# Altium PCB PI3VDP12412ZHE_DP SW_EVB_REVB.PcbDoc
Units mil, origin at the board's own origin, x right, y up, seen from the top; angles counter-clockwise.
Board outline 3198 x 2598 mil, 4 copper layers (Top Layer, InternalPlane1, InternalPlane2, Bottom Layer); 46 components, 59 nets, 210 pads, 109 vias.
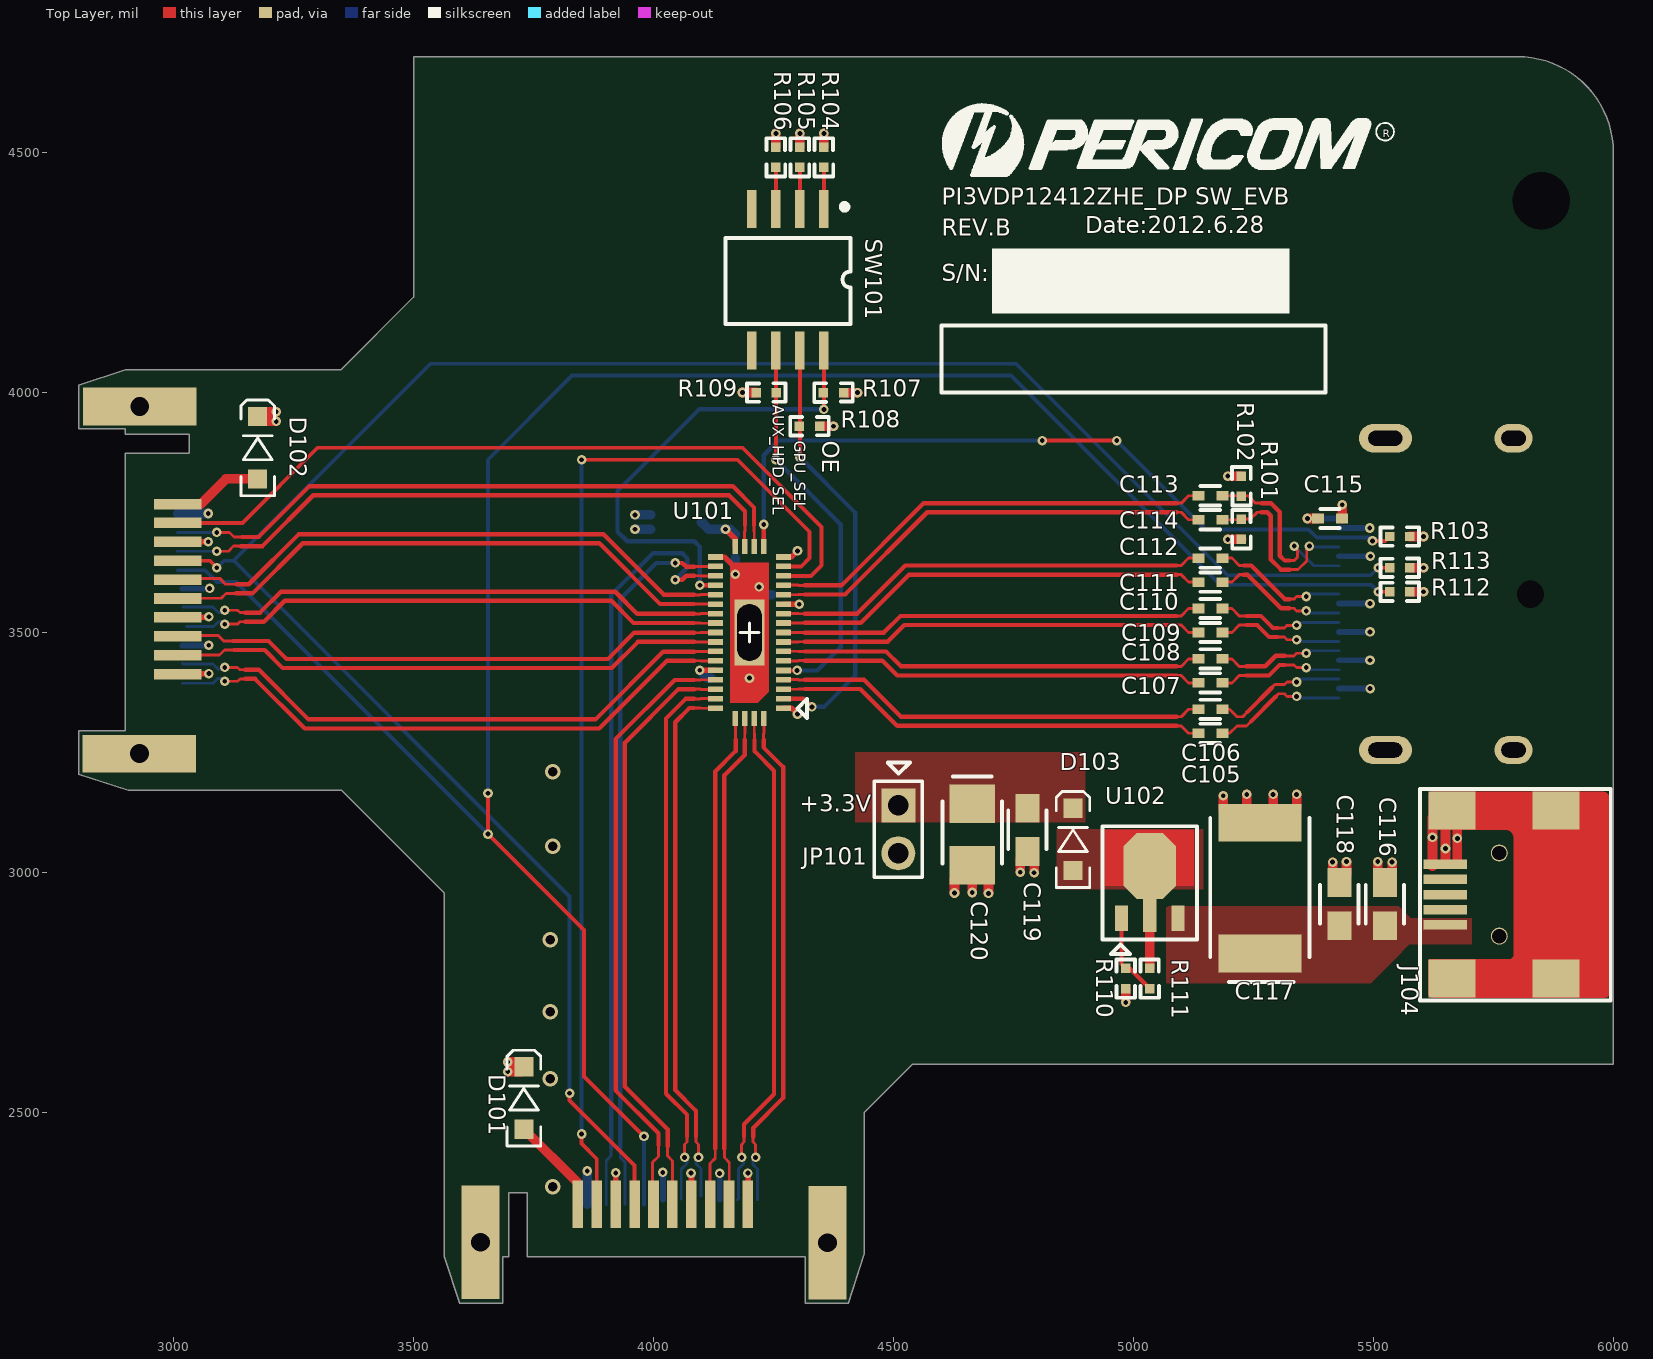
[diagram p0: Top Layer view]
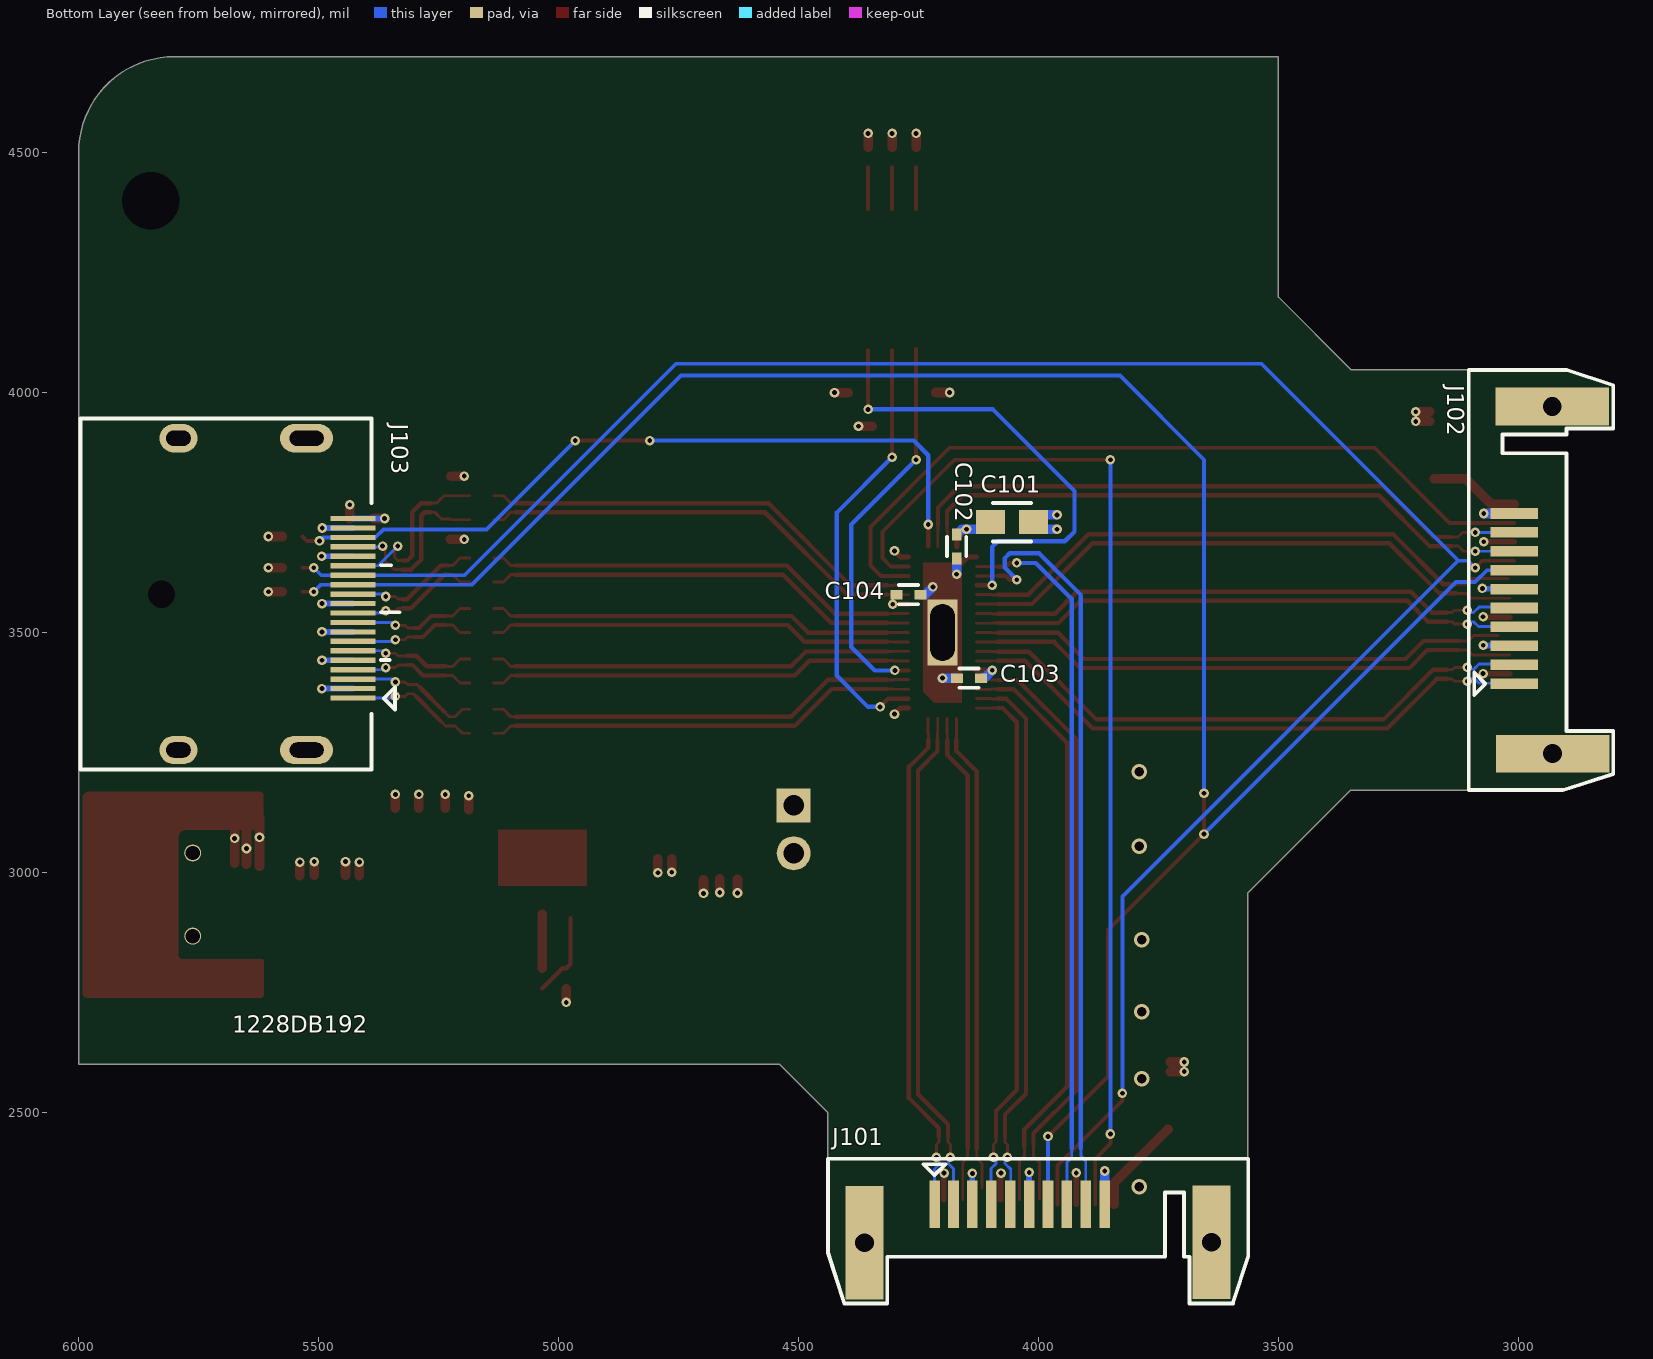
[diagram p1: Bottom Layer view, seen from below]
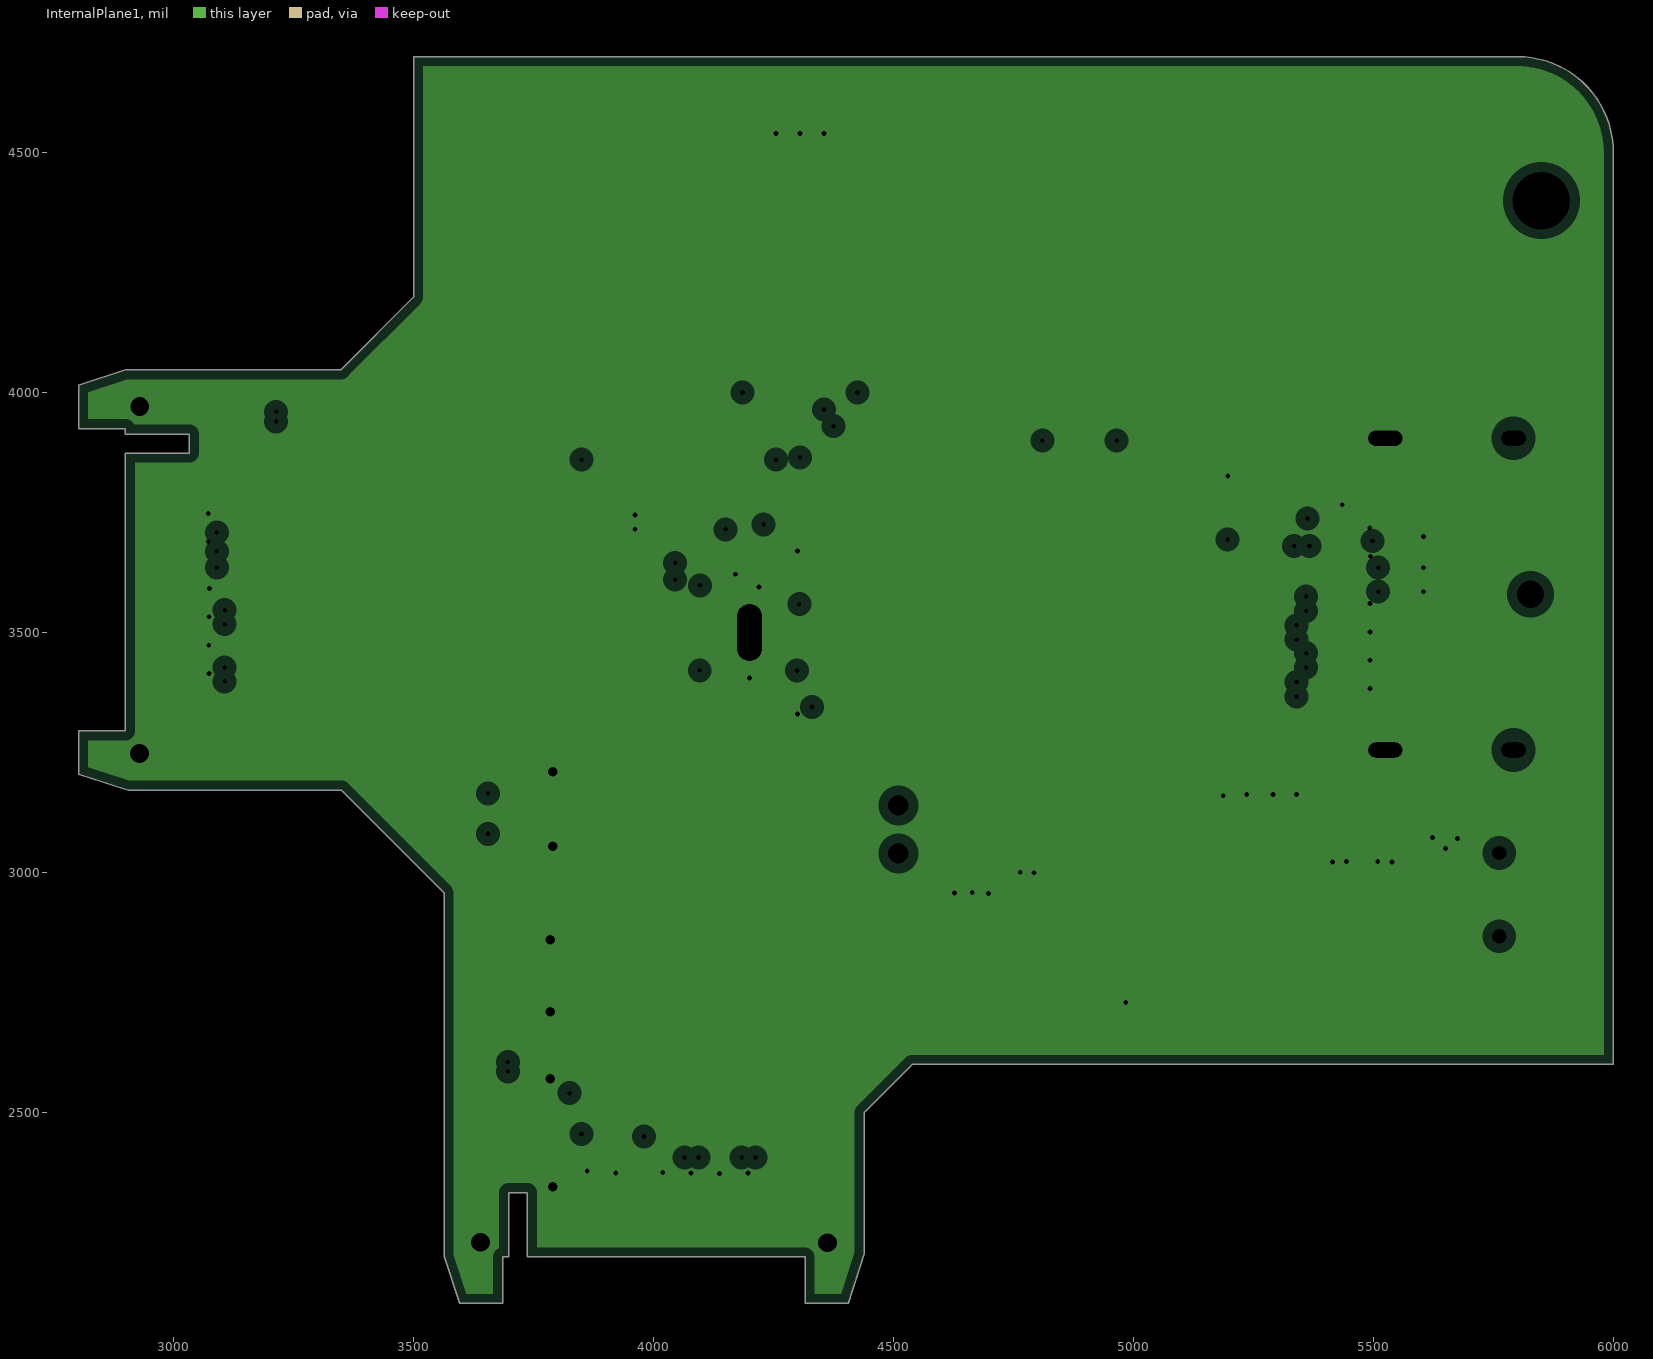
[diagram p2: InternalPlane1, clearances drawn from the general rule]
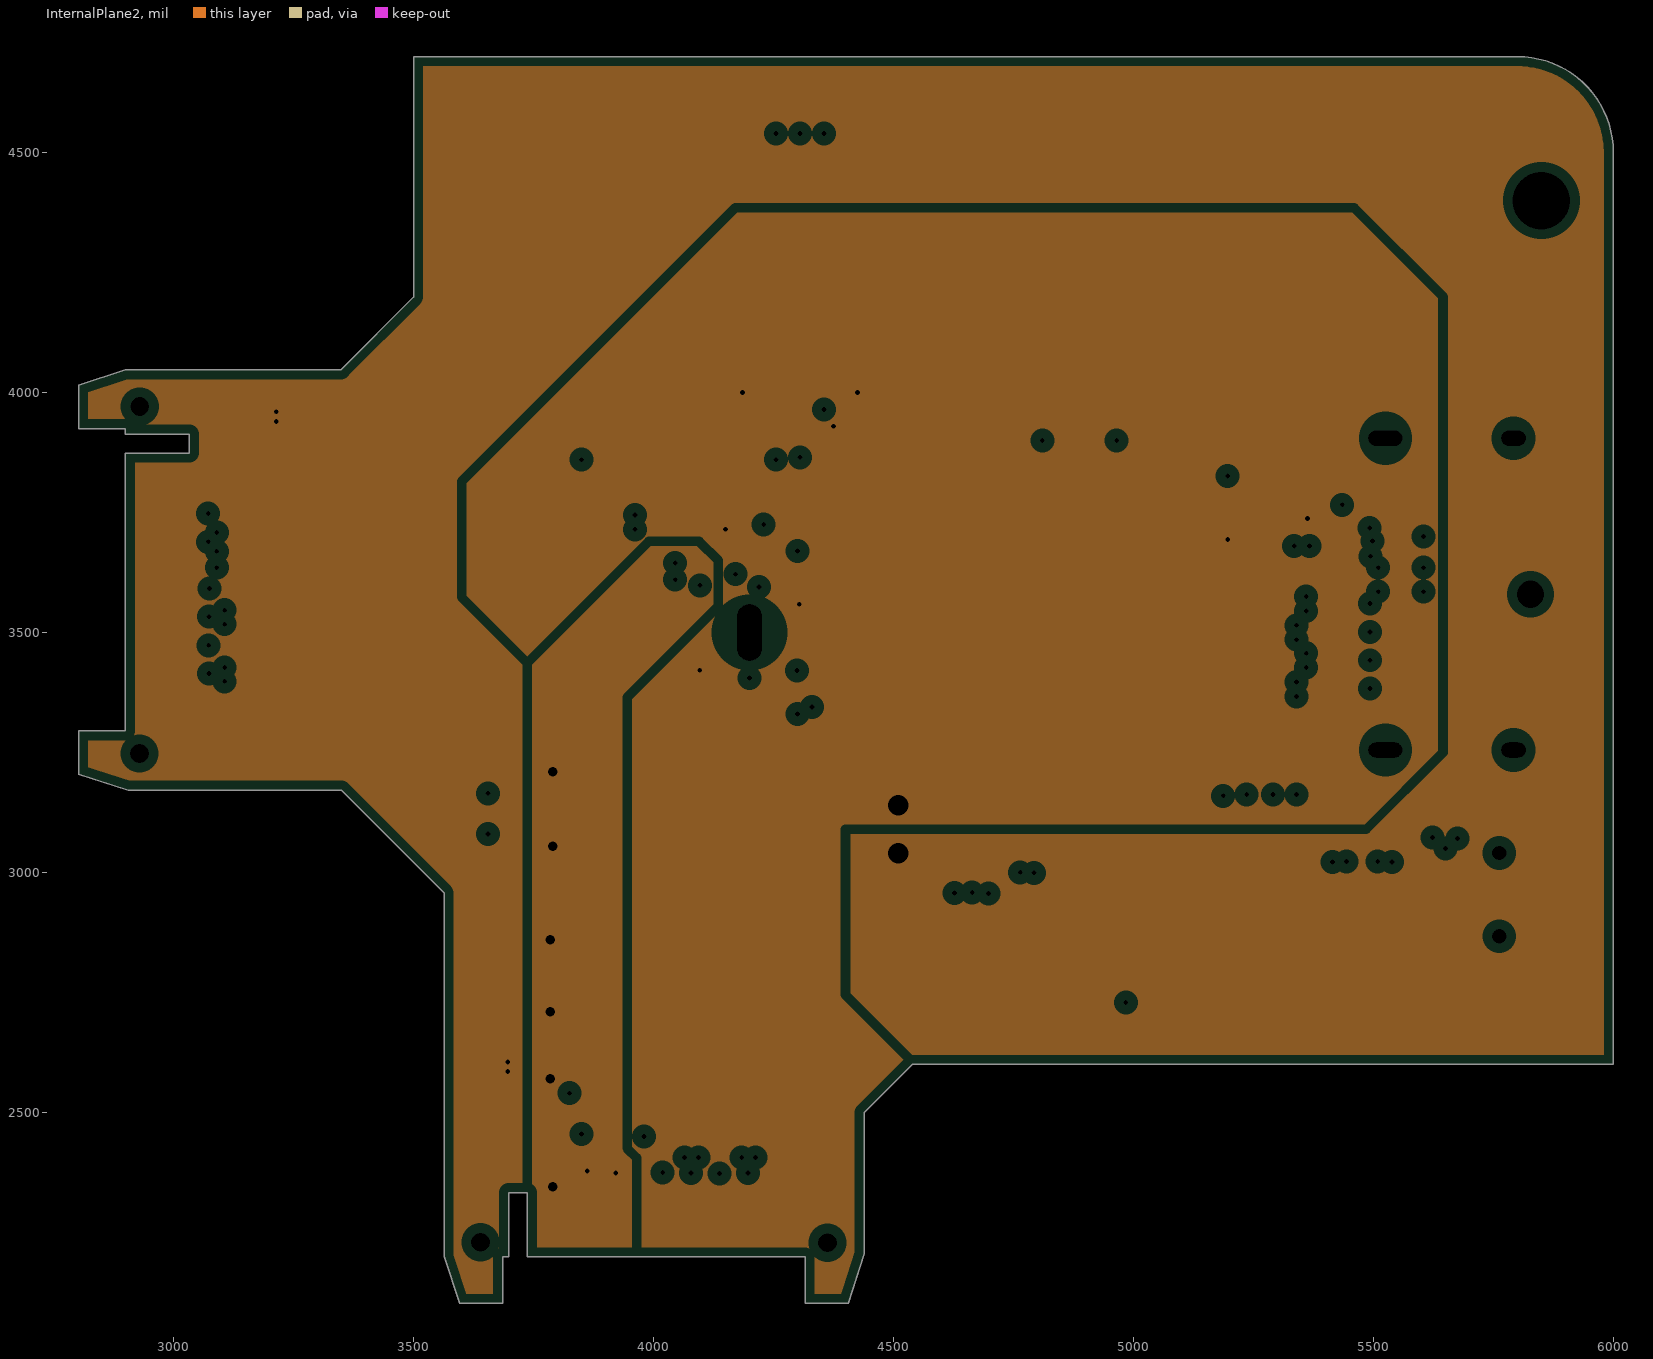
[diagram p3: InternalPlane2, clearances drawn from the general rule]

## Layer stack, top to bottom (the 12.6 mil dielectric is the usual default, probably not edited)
Top Layer: signal copper 1.4
Dielectric: core 12.6, FR-4, Dk 4.8
InternalPlane1: plane copper 1.4, net GND
Dielectric: prepreg 12.6, FR-4, Dk 4.8
InternalPlane2: plane copper 1.4, net +3V3
Dielectric: core 12.6, FR-4, Dk 4.8
Bottom Layer: signal copper 1.4

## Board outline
2802,3205 2802,3295 2899,3295 2899,3874 3033,3874 3033,3913 2899,3913 2899,3925 2802,3925 2802,4015 2899.9,4047.3 3348.3,4047.3 3500,4199 3500,4700 5800,4700 cw(c5800,4500) 6000,4500 6000,2600 4539,2600 4439,2500 4439,2205.6 4405.77,2102 4315.77,2102 4315.77,2199 3736.77,2199 3736.77,2333 3697.77,2333 3697.77,2199 3685.77,2199 3685.77,2102 3595.77,2102 3563.47,2199.9 3563.47,2957.53 3349.23,3171.77 2905.6,3171.77

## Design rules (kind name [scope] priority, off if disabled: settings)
Clearance [All] p1: gap=5
ComponentClearance [All] p1: gap=0 collisioncheckmode=3 verticalgap=0
DiffPairsRouting [All] p1: maxlimit=10 minlimit=10 mostfreqgap=10 maxuncoupledlength=500
PlaneClearance [All] p1: clearance=20
PlaneConnect [All] p1: planeconnectstyle=Direct reliefexpansion=20 reliefentries=4 reliefconductorwidth=10 reliefairgap=10
PolygonConnect [All] p1: connectstyle=Direct reliefconductorwidth=10 reliefentries=4 polygonreliefangle="90 Angle"
RoomDefinition "PI3VDP12412 EVB" [InComponentClass('PI3VDP12412 EVB')] p1: confinementstyle=ConfineIn formatcopy=TRUE lockcomponents=FALSE outline 55,960 20005,960 20005,7005 55,7005
RoutingVias [All] p1: holewidth=28 width=50 viastyle="Through Hole" minholewidth=8 minwidth=10 maxholewidth=28 maxwidth=50
SolderMaskExpansion [All] p1: expansion=4
TestPointUsage [All] p1: valid=0 allowmultiple=FALSE
Testpoint [All] p1: side=15 testpointundercomponent=TRUE minsize=40 maxsize=100 preferedsize=60 minholesize=0 maxholesize=40 preferedholesize=32 testpointgrid=1 style=1023 order=0123456789
Width [All] p1: maxlimit=105 minlimit=5 preferedwidth=10
15 further rules are at their usual default settings.

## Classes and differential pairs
differential pair NewDifferentialPair20: +NetC113_2 -NetC114_2
differential pair NewDifferentialPair19: +NetC111_2 -NetC112_2
differential pair NewDifferentialPair18: +NetC109_2 -NetC110_2
differential pair NewDifferentialPair17: +NetC107_2 -NetC108_2
differential pair NewDifferentialPair16: +NetC105_2 -NetC106_2
differential pair NewDifferentialPair15: +D3+B -D3-B
differential pair NewDifferentialPair14: +D3+A -D3-A
differential pair NewDifferentialPair13: +D3- -D3+
differential pair NewDifferentialPair12: +D2+B -D2-B
differential pair NewDifferentialPair11: +D2+A -D2-A
differential pair NewDifferentialPair10: +D2- -D2+
differential pair NewDifferentialPair9: +D1+B -D1-B
differential pair NewDifferentialPair8: +D1+A -D1-A
differential pair NewDifferentialPair7: +D1- -D1+
differential pair NewDifferentialPair6: +D0-B -D0+B
differential pair NewDifferentialPair5: +D0+A -D0-A
differential pair NewDifferentialPair4: +D0+ -D0-
differential pair NewDifferentialPair3: +AUX+B -AUX-B
differential pair NewDifferentialPair2: +AUX+A -AUX-A
differential pair NewDifferentialPair1: +AUX+ -AUX-

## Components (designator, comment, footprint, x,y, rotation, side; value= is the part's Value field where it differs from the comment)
C101 "4.7u" CC_0805 4055,3730 r0 bottom
C102 "1u" CC_0402 4170.47,3679.13 r90 bottom
C103 "0.1u" CC_0402 4145,3405 r180 bottom
C104 "0.1u" CC_0402 4270.87,3578.74 r0 bottom
C105 "0.1u" CC_0402 5160,3290 r0 top
C106 "0.1u" CC_0402 5160,3340 r0 top
C107 "0.1u" CC_0402 5160,3395 r0 top
C108 "0.1u" CC_0402 5160,3445 r0 top
C109 "0.1u" CC_0402 5160,3500 r0 top
C110 "0.1u" CC_0402 5160,3550 r0 top
C111 "0.1u" CC_0402 5160,3605 r0 top
C112 "0.1u" CC_0402 5160,3655 r0 top
C113 "0.1u" CC_0402 5160,3785 r0 top
C114 "0.1u" CC_0402 5160,3735 r0 top
C115 "0.1u" CC_0402 5410,3737.48 r180 top
C116 "4.7u" CC_0805 5524,2934 r90 top
C117 "100u" CAP@CT_7343 5264,2949 r270 top
C118 "1u" CAP@CC_0805 5429,2934 r90 top
C119 "1u" CAP@CC_0805 4779,3089 r270 top
C120 "22u" CAP@CT_3528 4664,3079 r270 top
D101 "B0520LW" D@SOD-123 3730,2530 r90 top
D102 "B0520LW" D@SOD-123 3175,3885 r90 top
D103 "B0520LW" D@SOD-123 4874,3069 r90 top
J101 "DP PLUG" CON_DP_PLUG 4000,2210 r0 bottom
J102 "DP PLUG" CON_DP_PLUG 2910,3610 r270 bottom
J103 "CON_DP_Source_Recept" CON_DP_Recept 5625,3580 r270 bottom
J104 "CON_USB2.0_MiniB_SMT" CON_USB2.0_MiniB_SMT 5969,2954 r180 top
JP101 "2x1 Pin Header" "2x1 Pin Header" 4510,3140 r270 top
R101 "100K" R_0402 5225,3805 r270 top
R102 "100K" R_0402 5225,3715 r90 top
R103 "100K" R_0402 5555,3700 r180 top
R104 "4K7" R_0402 4355,4490 r90 top
R105 "4K7" R_0402 4305,4490 r90 top
R106 "4K7" R_0402 4255,4490 r90 top
R107 "4K7" RES@R_0402 4375,4000 r0 top
R108 "4K7" RES@R_0402 4325,3930 r0 top
R109 "4K7" RES@R_0402 4235,4000 r180 top
R110 "0" RES@R_0402 4984,2779 r90 top
R111 "NP" RES@R_0402 5034,2779 r90 top
R112 "1M" RES@R_0402 5555,3585 r180 top
R113 "1M" RES@R_0402 5555,3635 r180 top
SW101 "SW_X4_Half_Pitch" SW_X4_Half_Pitch 4280,4235 r180 top
U101 "PI3VDP12412" TQFN42 4200,3500 r90 top locked
U102 "REG1117-3.3V" Pow_SOT_89 5034,2959 r0 top
? "Comment" PSC_LOG 4710,4555 r0 top
? "" "Lable Hole" 5850,4400 r0 top

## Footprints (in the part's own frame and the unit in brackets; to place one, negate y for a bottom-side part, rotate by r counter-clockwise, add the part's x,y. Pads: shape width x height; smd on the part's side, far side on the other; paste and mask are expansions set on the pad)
"2x1 Pin Header" [mm] "Pin Header 2x1 Pitch 2.54mm"
  rect 1.8x1.8 hole 1.1: 1(0,0)
  round 1.8 hole 1.1: 2(2.54,0)
  silkscreen extent -2.27,-1.27 3.81,1.27
CAP@CC_0805 [mil]
  rect 60x50 smd: 1(-45,0) 2(45,0)
  silkscreen extent -40,-40 40,40
CAP@CT_3528 [mil]
  rect 80x95 smd: 1(-64,0) 2(64,0)
  silkscreen extent -121,-62 60,62
CAP@CT_7343 [mm]
  rect 2x4.4 smd: 1(3,0) 2(-3.926,-0.011)
  silkscreen extent -4.19,-2.64 4.5,2.62
CC_0402 [mil]
  rect 25x20 smd: 1(-25,0) 2(25,0)
  silkscreen extent -20,-20 20,20
CC_0805 [mil]
  rect 60x50 smd: 1(-45,0) 2(45,0)
  silkscreen extent -40,-40 40,40
CON_DP_PLUG [mm]
  rect 0.56x2.5 smd: 1(5.495,-2.5) 3(4.495,-2.5) 5(3.495,-2.5) 7(2.495,-2.5) 9(1.495,-2.5) 11(0.495,-2.5) 13(-0.505,-2.5) 15(-1.505,-2.5) 17(-2.505,-2.5) 19(-3.505,-2.5)
  rect 0.56x2.5 smd far side: 2(4.995,-2.5) 4(3.995,-2.5) 6(2.995,-2.5) 8(1.995,-2.5) 10(0.995,-2.5) 12(-0.005,-2.5) 14(-1.005,-2.5) 16(-2.005,-2.5) 18(-3.005,-2.5) 20(-4.005,-2.5)
  rect 2x6 hole 1: 21(-9.166,-0.493) 21(9.206,-0.469)
  silkscreen extent -11.11,-4.92 11.14,2.74
CON_DP_Recept [mm]
  rect 0.28x2.4 smd: 1(5.5,5) 2(5,5) 3(4.5,5) 4(4,5) 5(3.5,5) 6(3,5) 7(2.5,5) 8(2,5) 9(1.5,5) 10(1,5) 11(0.5,5) 12(0,5) 13(-0.5,5) 14(-1,5) 15(-1.5,5) 16(-2,5) 17(-2.5,5) 18(-3,5) 19(-3.5,5) 20(-4,5)
  oval 1.5x2.8 hole 0.8 slot 1.8 at 90 deg: 21(-8.25,2.54) 22(8.25,2.54)
  oval 1.5x2 hole 0.8 slot 1.3 at 90 deg: 23(-8.25,-4.24) 24(8.25,-4.24)
  round 0 hole 1.45 unplated: 25(0,-5.14)
  silkscreen extent -9.29,-9.42 9.28,7.47
CON_USB2.0_MiniB_SMT [mm]
  rect 2.3x0.5 smd: 1(8.1,1.6) 2(8.1,0.8) 3(8.1,0) 4(8.1,-0.8) 5(8.1,-1.6)
  rect 2.5x2 smd: 5(2.25,4.45) 5(2.25,-4.45) 5(7.75,-4.45) 5(7.75,4.45)
  round 0.9 hole 0.762 unplated: 10(5.25,-2.2) 11(5.25,2.2)
  Top Layer region: 1.58,5.45 -0.35,5.45 -0.438,5.432 -0.513,5.383 -0.562,5.308 -0.58,5.22 -0.58,5.22 -0.58,-5.09 -0.553,-5.224 -0.477,-5.337 -0.364,-5.413 -0.23,-5.44 -0.23,-5.44 8.81,-5.44 8.875,-5.427 8.93,-5.39 8.967,-5.335 8.98,-5.27 8.98,-5.27 8.98,-3.59 8.968,-3.529 8.933,-3.477 8.881,-3.442 8.82,-3.43 8.82,-3.43 4.93,-3.43 4.758,-3.396 4.612,-3.298 4.514,-3.152 4.48,-2.98 4.48,-2.98 4.48,3.17 4.5,3.269 4.556,3.354 4.641,3.41 4.74,3.43 4.74,3.43 8.93,3.43 8.964,3.437 8.994,3.456 9.013,3.486 9.02,3.52 9.02,3.52 9.02,5.26 9.004,5.34 8.958,5.408 8.89,5.454 8.81,5.47 8.81,5.47 1.6,5.47 1.592,5.468 1.586,5.464 1.582,5.458 1.58,5.45
  silkscreen extent -0.65,-5.59 9.45,5.6
D@SOD-123 [mil]
  rect 40x40 smd: 1(-65,0) 2(65,0)
  silkscreen extent -100,-35 100,35
"Lable Hole" [mil]
  round 0 hole 120 unplated: ""(0,0)
Pow_SOT_89 [mm] "SOT-89; Body 4.6 x 4.25 mm, inc. leads (LxW max)"
  rect 0.7x1.35 smd: 1(-1.5,-1.388) 3(1.5,-1.388)
  rect 0.7x1.9 smd: 2(0,-1.163)
  oct 2.8x3.5 smd: 2(0,1.388)
  Top Layer region: -2.346,0.336 -2.346,3.302 2.322,3.302 2.323,3.303 2.323,0.338 2.325,0.336
  silkscreen extent -2.5,-3.28 2.5,3.49
PSC_LOG [mil]
  silkscreen extent -107,-103 833,45
R_0402 [mm]
  rect 0.5x0.5 smd: 1(-0.532,-0.001) 2(0.54,-0.001)
  silkscreen extent -1.02,-0.49 1.02,0.49
RES@R_0402 [mm]
  rect 0.5x0.5 smd: 1(-0.532,-0.001) 2(0.54,-0.001)
  silkscreen extent -1.02,-0.49 1.02,0.49
SW_X4_Half_Pitch [mm]
  rect 0.5x2 smd: 1(-1.905,-3.75) 2(-0.635,-3.75) 3(0.635,-3.75) 4(1.905,-3.75) 5(1.905,3.75) 6(0.635,3.75) 7(-0.635,3.75) 8(-1.905,3.75)
  silkscreen extent -3.31,-4.01 3.31,2.34
TQFN42 [mm]
  rect 0.3x0.8 smd: 1(-4,-1.8) 2(-3.5,-1.8) 3(-3,-1.8) 4(-2.5,-1.8) 5(-2.007,-1.8) 6(-1.5,-1.8) 7(-1,-1.8) 8(-0.5,-1.8) 9(0,-1.8) 10(0.5,-1.8) 11(1,-1.8) 12(1.5,-1.8) 13(2,-1.8) 14(2.5,-1.8) 15(3,-1.8) 16(3.5,-1.8) 17(4,-1.8) 22(4,1.8) 23(3.5,1.8) 24(3,1.8) 25(2.5,1.8) 26(2.007,1.8) 27(1.5,1.8) 28(1,1.8) 29(0.5,1.8) 30(0,1.8) 31(-0.5,1.8) 32(-1,1.8) 33(-1.5,1.8) 34(-2,1.8) 35(-2.5,1.8) 36(-3,1.8) 37(-3.5,1.8) 38(-4,1.8)
  rect 0.8x0.3 smd: 18(4.55,-0.75) 19(4.55,-0.25) 20(4.55,0.25) 21(4.55,0.75) 39(-4.55,0.75) 40(-4.55,0.25) 41(-4.55,-0.25) 42(-4.55,-0.75)
  rect 3.5x1.6 hole 1.3 slot 3 at 0 deg: 43(0,0)
  Top Layer region: -3.72,1.01 3.7,1.01 3.7,-1.01 -3.14,-1.01 -3.72,-0.43
  silkscreen extent -4.52,-3.05 0.5,0.5

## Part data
C101 C102 C103 C104 C105 C106 C107 C108 C109 C110 C111 C112 C113 C114 C115: library part C_0.1u_0402
C116 C118 C119: library part "CHIP CAP0805"
C117: library part "100UF 7343_1"
C120: library part "22UF 3528"
D101 D102 D103: library part SchottkyDiode@SOD-123_1
J101: library part CONN_DP_1
J102: library part CONN_DP_0
J103: library part CON_DP_Source_Recept_1
R101 R102 R103 R104 R105 R106: library part R_0402
R107 R108 R109 R110 R111 R112 R113: library part "CHIP RES0402_1"
U101: library part PI3PCIE3412ZHE@TQFN42_1
U102: library part REG1117ADJ@SOT89

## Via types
v1: diameter 20, hole 10, Top Layer to Bottom Layer, tented both sides, 103 vias
v2: diameter 32, hole 20, Top Layer to Bottom Layer, tented both sides, 6 vias

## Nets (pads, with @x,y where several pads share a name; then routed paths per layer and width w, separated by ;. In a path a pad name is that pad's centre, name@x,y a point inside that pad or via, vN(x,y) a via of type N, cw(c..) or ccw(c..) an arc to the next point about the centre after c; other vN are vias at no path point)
+3V3: C101.2 C102.2 C103.2 C104.2 C115.2 C119.1 C120.1 D103.2 J103.20 JP101.1 R102.1 R107.2 R108.2 R109.2 U101.12 U101.21 U101.34 | length 424.7
  Top Layer w12: v1(4096.26,3421.26) U101.34 ; v1(4150,3715) 4170.47,3694.53 U101.21 ; U101.12 v1(4303.74,3559.05)
  Top Layer w20: v1(4185.03,4000.03) R109.2 ; R108.2 v1(4374.97,3929.97) ; R107.2 v1(4424.97,3999.97) ; v1(5196.33,3694.05) R102.1 ; v1(5362.48,3737.48) C115.2
  Bottom Layer w12: v1(5362.48,3737.48) J103.20
  Bottom Layer w20: v1(4096.26,3421.26) 4112.52,3405 C103.2 ; C101.2 4115,3715 4159.61,3715 C102.2
+3V3_A: D101.1 J101.20 | length 203.1
  Top Layer w20: D101.1 3842.32,2352.68 J101.20
+3V3_B: D102.1 J102.20 | length 188.2
  Top Layer w20: J102.20 3056.6,3767.68 3108.92,3820 D102.1
+3V3_USB: D103.1 R111.2 U102.2 | length 112.9
  Top Layer w20: R111.2 U102.2@5034.03,2913.18
+5V: C116.1 C117.1 C118.1 J104.1 U102.3
AUX+: C113.1 U101.14 | length 941.7
  Top Layer w6: U101.14@4270.87,3598.7 4301.61,3598.7 4302.09,3598.22 4314.94,3598.22 ; 5089.93,3769.5 5099.5,3769.5 5115,3785 C113.1
  Top Layer w9: 4314.94,3598.22 4391.35,3598.22 4562.63,3769.5 5089.93,3769.5
AUX+A: J101.15 U101.23 | length 1498.8
  Top Layer w6: 4085.06,3637.32 4097.91,3637.32 4098.39,3637.8 U101.23
  Top Layer w9: v1(4045,3645) 4060,3645 4065,3640 4067.68,3637.32 4085.06,3637.32
  Bottom Layer w6: 3930.56,2425.2 3930.56,2406.49 3940.75,2396.3 J101.15
  Bottom Layer w9: 3930.56,2425.2 3930.56,3535.56 3930.56,3570.06 4005.5,3645 v1(4045,3645)
AUX+B: J102.15 U101.20 | length 1317.9
  Top Layer w6: v1(3090,3669.25) 3114.25,3669.25 3125,3680 3140.03,3680 ; U101.20@4189.88,3679.13 4189.88,3709.88 4190.36,3710.36 4190.36,3723.21
  Top Layer w9: 3140.03,3680 3185,3680 3291.01,3786 4157.13,3786 4190.36,3752.77 4190.36,3723.21
  Bottom Layer w6: J102.15 v1(3090,3669.25)
AUX-: C114.1 U101.13 | length 941.7
  Top Layer w6: U101.13 4301.61,3578.74 4302.09,3579.22 4314.94,3579.22 ; 5090.06,3750.5 5099.5,3750.5 5115,3735 C114.1
  Top Layer w9: 4314.94,3579.22 4399.22,3579.22 4570.5,3750.5 5090.06,3750.5
AUX-A: J101.17 U101.24 | length 1615.8
  Top Layer w6: 4085.06,3618.32 4097.91,3618.32 4098.39,3617.83 U101.24@4129.13,3617.83
  Top Layer w9: v1(4045,3610) 4060,3610 4068.31,3618.31 4085.06,3618.32
  Bottom Layer w6: J101.17 3901.38,2399.46 3911.56,2409.65 3911.56,2425.47
  Bottom Layer w9: 3911.56,2425.2 3911.56,3543.43 3911.56,3577.93 3998.63,3665 4060,3665 4070,3655 4070,3635 v1(4045,3610)
AUX-B: J102.17 U101.19 | length 1348.9
  Top Layer w6: v1(3090,3708.62) 3116.38,3708.62 3126,3699 3141.99,3699 ; 4209.36,3723.21 4209.36,3710.36 4209.84,3709.88 U101.19
  Top Layer w9: 3141.99,3699 3177.13,3699 3283.14,3805 4165,3805 4209.36,3760.64 4209.36,3723.21
  Bottom Layer w6: J102.17 v1(3090,3708.62)
AUX_HPD_SEL: R109.1 SW101.6 U101.5 | length 815.4
  Top Layer w9: v1(4255,3860) SW101.6@4255,4090 ; U101.5 v1(4299.02,3420.98)
  Bottom Layer w9: v1(4255,3860) 4390,3725 4390,3470 4340.98,3420.98 v1(4299.02,3420.98)
CAB_DET: J101.13 J102.13 J103.13 R112.2 | length 4698.4
  Top Layer w8: v1(3655,3165) v1(3655,3080) 3855,2880 3855,2575.12 v1(3980.12,2450) ; v1(5510,3585) R112.2
  Bottom Layer w8: J102.13 3065.12,3629.88 3090,3605 3130,3605 v1(3655,3080) ; v1(3655,3165) 3655,3860 3830.25,4035.25 4744.75,4035.25 5180.31,3599.68 5495.31,3599.68 v1(5510,3585) ; J101.13 v1(3980.12,2450)
CEC: J101.14 J102.14 J103.14 R113.2 | length 4583.3
  Top Layer w8: J102.14 3075.43,3649.57 v1(3090,3635) ; v1(3825,2540) 3825,2525 3960.43,2389.57 J101.14 ; v1(5510,3635) R113.2
  Bottom Layer w8: v1(3090,3635) 3104.57,3649.57 3124.57,3649.57 3535,4060 4755,4060 5195.63,3619.37 J103.14 5494.37,3619.37 v1(5510,3635) ; 3125.43,3649.57 3825,2950 v1(3825,2540)
D0+: C105.1 U101.3 | length 902.5
  Top Layer w6: U101.3 4301.61,3381.89 4302.09,3382.37 4314.94,3382.37 ; 5090.06,3305.5 5099.5,3305.5 5115,3290 C105.1
  Top Layer w9: 4314.94,3382.37 4430.76,3382.37 4507.63,3305.5 5089.93,3305.5
D0+A: J101.1 U101.42 | length 1054.5
  Top Layer w6: 4207.6,2449.39 4207.6,2438.39 4212.6,2433.39 v1(4212.6,2406.39) ; 4229.32,3276.79 4229.32,3289.64 4229.8,3290.12 U101.42@4229.8,3320.87
  Top Layer w9: 4207.6,2449.39 4207.6,2467.6 4270,2530 4270,3220 4229.32,3260.68 4229.32,3276.79
  Bottom Layer w6: v1(4212.6,2406.39) 4206.61,2400.4 4206.61,2392 4216.8,2381.82 J101.1@4216.8,2318
D0+B: J102.1 U101.33 | length 1221.4
  Top Layer w6: v1(3106.39,3398.4) 3133.39,3398.4 3138.39,3403.4 3149.39,3403.4 ; 4085.06,3441.15 4097.91,3441.15 4098.39,3440.67 U101.33@4129.13,3440.67
  Top Layer w9: 3149.39,3403.4 3169.73,3403.4 3273.13,3300 3886.87,3300 4028.02,3441.15 4085.06,3441.15
  Bottom Layer w6: J102.1@3018,3394.2 3081.82,3394.2 3092,3404.39 3100.4,3404.39 v1(3106.39,3398.4)
D0-: C106.1 U101.4 | length 902.6
  Top Layer w6: U101.4@4270.87,3401.85 4301.61,3401.85 4302.09,3401.37 4314.94,3401.37 ; 5089.93,3324.5 5099.5,3324.5 5115,3340 C106.1
  Top Layer w9: 4314.94,3401.37 4438.63,3401.37 4515.5,3324.5 5089.93,3324.5
D0-A: J101.3 U101.41 | length 1054.7
  Top Layer w6: v1(4183.6,2406.39) 4183.6,2433.39 4188.6,2438.39 4188.6,2449.39 ; U101.41 4209.84,3290.12 4210.32,3289.64 4210.32,3276.79
  Top Layer w9: 4188.6,2449.39 4188.6,2475.47 4251,2537.87 4251,3212.13 4210.32,3252.81 4210.32,3276.79
  Bottom Layer w6: J101.3@4175.11,2318 4176.61,2319.5 4176.61,2382 4187.61,2393 4187.61,2402.37 v1(4183.6,2406.39)
D0-B: J102.3 U101.32 | length 1221.5
  Top Layer w6: v1(3106.39,3427.4) 3133.39,3427.4 3138.39,3422.4 3149.39,3422.4 ; 4085,3460.15 4097.91,3460.15 4098.39,3460.63 U101.32
  Top Layer w9: 3149.39,3422.4 3177.6,3422.4 3281,3319 3879,3319 4020.15,3460.15 4085,3460.15
  Bottom Layer w6: J102.3@3018,3435.89 3019.5,3434.39 3082,3434.39 3093,3423.39 3102.37,3423.39 v1(3106.39,3427.4)
D1+: C107.1 U101.6 | length 883.4
  Top Layer w6: U101.6 4301.61,3440.94 4302.09,3441.43 4314.94,3441.43 ; 5090.06,3410.5 5099.5,3410.5 5115,3395 C107.1
  Top Layer w9: 4314.94,3441.43 4476.7,3441.43 4507.63,3410.5 5089.93,3410.5
D1+A: J101.4 U101.40 | length 1024.8
  Top Layer w6: 4147.56,2425 4147.56,2406 4157.74,2395.82 J101.4@4157.74,2318 ; 4189.95,3276.79 4189.95,3289.64 4190.43,3290.12 U101.40@4190.43,3320.87
  Top Layer w9: 4147.55,2425 4147.56,3202.56 4189.95,3244.95 4189.95,3276.79
D1+B: J102.4 U101.31 | length 1153.6
  Top Layer w6: J102.4@3018,3453.26 3095.82,3453.26 3106,3463.44 3125,3463.44 ; 4085.06,3480.52 4097.91,3480.52 4098.39,3480.04 U101.31@4129.13,3480.04
  Top Layer w9: 3125,3463.44 3156.47,3463.44 3189.69,3463.44 3227.13,3426 3912.87,3426 3967.39,3480.52 4085.06,3480.52
D1-: C108.1 U101.7 | length 883.6
  Top Layer w6: U101.7@4270.87,3460.91 4301.61,3460.91 4302.09,3460.43 4315,3460.43 ; 5089.93,3429.5 5099.5,3429.5 5115,3445 C108.1
  Top Layer w9: 4315,3460.43 4484.57,3460.43 4515.5,3429.5 5089.93,3429.5
D1-A: J101.6 U101.39 | length 999.3
  Top Layer w6: J101.6@4117.61,2342.5 4117.61,2393.57 4128.56,2404.51 4128.56,2423.68 ; U101.39 4170.47,3290.12 4170.95,3289.64 4170.95,3276.79
  Top Layer w9: 4128.55,2425 4128.56,3210.43 4170.95,3252.82 4170.95,3276.79
D1-B: J102.6 U101.30 | length 1129.5
  Top Layer w6: J102.6@3042.5,3493.39 3093.57,3493.39 3104.51,3482.44 3123.68,3482.44 ; 4085.06,3499.52 4097.91,3499.52 4098.39,3500 U101.30
  Top Layer w9: 3123.68,3482.44 3197.56,3482.45 3235,3445 3905,3445 3959.52,3499.52 4085.06,3499.52
D2+: C109.1 U101.8 | length 885
  Top Layer w6: U101.8 4301.61,3480.32 4302.09,3480.8 4314.94,3480.8 ; 5090.06,3515.5 5099.5,3515.5 5115,3500 C109.1
  Top Layer w9: 4314.94,3480.8 4487.67,3480.8 4522.37,3515.5 5089.93,3515.5
D2+A: J101.7 U101.38 | length 1109.7
  Top Layer w6: 4085.06,3342.72 4097.91,3342.72 4098.39,3342.24 U101.38@4129.13,3342.24 ; 4088.6,2449.39 4088.6,2438.39 4093.6,2433.39 v1(4093.6,2406.39)
  Top Layer w9: 4085.06,3342.72 4074.59,3342.72 4045,3313.13 4045,2546.87 4088.6,2503.27 4088.6,2480.15 4088.6,2449.39
  Bottom Layer w6: v1(4093.6,2406.39) 4088.5,2401.29 4088.5,2393.18 4098.69,2383 J101.7@4098.69,2326.5
D2+B: J102.7 U101.29 | length 1148.4
  Top Layer w6: v1(3106.39,3517.4) 3133.39,3517.4 3138.39,3522.4 3149.39,3522.4 ; 4085.06,3519.89 4097.91,3519.89 4098.39,3519.41 U101.29@4129.13,3519.41
  Top Layer w9: 3149.39,3522.4 3188.02,3522.4 3231.62,3566 3912.13,3566 3958.24,3519.89 4085.06,3519.89
  Bottom Layer w6: J102.7@3026.5,3512.31 3083,3512.31 3093.18,3522.5 3101.29,3522.5 v1(3106.39,3517.4)
D2-: C110.1 U101.9 | length 885.1
  Top Layer w6: U101.9@4270.87,3500.28 4301.61,3500.28 4302.09,3499.8 4314.94,3499.8 ; 5089.93,3534.5 5099.5,3534.5 5115,3550 C110.1
  Top Layer w9: 4314.94,3499.8 4479.8,3499.8 4514.5,3534.5 5089.93,3534.5
D2-A: J101.9 U101.37 | length 1148.6
  Top Layer w6: v1(4064.6,2406.39) 4064.6,2433.39 4069.6,2438.39 4069.6,2449.39 ; 4085.06,3361.72 4097.91,3361.72 4098.39,3362.2 U101.37
  Top Layer w9: 4069.6,2449.39 4069.6,2495.4 4026,2539 4026,3321 4066.72,3361.72 4085.06,3361.72
  Bottom Layer w6: J101.9@4057.61,2319.7 4057.61,2381.5 4069.5,2393.39 4069.5,2401.48 v1(4064.6,2406.39)
D2-B: J102.9 U101.28 | length 1155.8
  Top Layer w6: v1(3106.39,3546.4) 3133.39,3546.4 3138.39,3541.4 3149.39,3541.4 ; 4085.06,3538.89 4097.91,3538.89 4098.39,3539.37 U101.28
  Top Layer w9: 3149.39,3541.4 3180.15,3541.4 3223.75,3585 3920,3585 3966.11,3538.89 4085.06,3538.89
  Bottom Layer w6: J102.9@3019.7,3553.39 3081.5,3553.39 3093.39,3541.5 3101.48,3541.5 v1(3106.39,3546.4)
D3+: C111.1 U101.10 | length 912.3
  Top Layer w6: U101.10 4301.61,3519.68 4302.09,3520.17 4314.94,3520.17 ; 5090.06,3620.5 5099.5,3620.5 5115,3605 C111.1
  Top Layer w9: 4314.94,3520.17 4432.04,3520.17 4532.37,3620.5 5090.06,3620.5
D3+A: J101.10 U101.36 | length 1229
  Top Layer w6: 4029.45,2429.77 4029.45,2409.25 4039.63,2399.07 J101.10@4039.63,2318 ; 4085.06,3382.09 4097.91,3382.09 4098.39,3381.61 U101.36@4129.13,3381.61
  Top Layer w9: 4029.45,2429.77 4029.45,2464.41 3940,2553.85 3940,3270 4052.09,3382.09 4085.06,3382.09
D3+B: J102.10 U101.27 | length 1211.2
  Top Layer w6: J102.10@3018,3571.37 3099.07,3571.37 3109.25,3581.55 3129.77,3581.55 ; 4085.06,3559.54 4097.91,3559.54 4098.39,3559.06 U101.27
  Top Layer w9: 3129.77,3581.55 3164.41,3581.55 3268.86,3686 3887.13,3686 4013.59,3559.54 4085.06,3559.54
D3-: C112.1 U101.11 | length 912.3
  Top Layer w6: U101.11@4270.87,3539.65 4301.61,3539.65 4302.09,3539.17 4314.94,3539.17 ; 5089.93,3639.5 5099.5,3639.5 5115,3655 C112.1
  Top Layer w9: 4314.94,3539.17 4424.17,3539.17 4524.5,3639.5 5089.93,3639.5
D3-A: J101.12 U101.35 | length 1259.3
  Top Layer w6: J101.12@3998.11,2320.15 3998.11,2396 4010.45,2408.33 4010.45,2431.35 ; 4085.06,3401.09 4097.91,3401.09 4098.39,3401.57 U101.35
  Top Layer w9: 4010.45,2431.35 4010.44,2456.54 3921,2545.98 3921,3277.87 4044.22,3401.09 4085.06,3401.09
D3-B: J102.12 U101.26 | length 1209.9
  Top Layer w6: J102.12@3020.15,3612.89 3096,3612.89 3108.33,3600.55 3131.35,3600.55 ; 4085.06,3578.54 4097.91,3578.54 4098.39,3579.02 U101.26
  Top Layer w9: 3131.35,3600.55 3156.54,3600.56 3260.99,3705 3895,3705 4021.46,3578.54 4085.06,3578.54
GND: C101.1 C102.1 C103.1 C104.1 C115.1 C116.2 C117.2 C118.2 C119.2 C120.2 J101.2 J101.5 J101.8 J101.11 J101.16 J101.19 J101.21 J102.2 J102.5 J102.8 J102.11 J102.16 J102.19 J102.21 J103.2 J103.5 J103.8 J103.11 J103.16 J103.19 J103.21 J103.22 J104.5 R101.1 R103.1 R104.2 R105.2 R106.2 R110.1 R112.1 R113.1 U101.1 U101.17 U101.22 U101.43 | length 2315
  Top Layer w11: U101.22 4147.52,3657.48 v1@4175,3630 ; U101.1 4287.48,3342.52 v1(4300,3330) ; U101.17 4287.48,3657.48 v1(4300,3670)
  Top Layer w12: J102.16@3008.49,3689 v1(3072,3689) ; J102.2@3018,3413.89 v1@3073,3413.89 ; J102.8@3018,3532 v1@3072.61,3532 ; J101.16 v1(3921.06,2373.94) ; J101.8@4079,2318 v1@4079,2372.61 ; J101.2@4197.11,2318 v1@4197.11,2373
  Top Layer w20: R106.2 v1(4255.03,4539.97) ; R105.2 v1(4305.03,4539.97) ; R104.2 v1(4355.03,4539.97) ; v1(4627,2957.3) C120.2@4627,2986 ; v1(4664,2958.3) C120.2@4664,2987 ; v1(4698,2956.3) C120.2@4698,2985 ; v1(4764,3000.3) C119.2@4764,3029 ; v1(4793,2999.3) C119.2@4793,3028 ; v1(4984.03,2729.35) R110.1 ; C117.2@5187,3131 v1(5187,3159.7) ; v1(5196.27,3825.95) R101.1 ; C117.2@5236,3134 v1(5236,3162.7) ; C117.2@5291,3134 v1(5291,3162.7) ; C117.2@5340,3134 v1(5340,3162.7) ; C118.2@5415,2993 v1(5415,3021.7) ; C115.1 v1(5435,3766.18) ; C118.2@5444,2994 v1(5444,3022.7) ; C116.2@5509,2994 v1(5509,3022.7) ; C116.2@5539,2993 v1(5539,3021.7) ; R112.1 v1(5604.65,3585.03) ; R113.1 v1(5604.65,3635.03) ; R103.1 v1(5604.65,3700.03) ; J104.5@5623,3013 J104.5@5623,3115 ; J104.5@5650.1,3016.99 J104.5@5650.1,3122.9 ; J104.5@5675,3019 J104.5@5675,3117
  Bottom Layer w12: J102.5@3018,3472.94 v1@3072.56,3472.94 ; J102.11@3018,3591.06 v1@3074.17,3591.06 ; J101.11@4019.94,2318 v1@4019.94,2374.17 ; J101.5@4138.06,2318 v1@4138.06,2372.56 ; J103.2 v1(5493.15,3383.15) ; J103.5 v1(5492.8,3442.2) ; J103.8 v1(5492.8,3501.26) ; J103.11 v1(5492.8,3560.31) ; J103.16 v1(5493.74,3658.74) ; J103.19 v1(5492.2,3717.8)
  Bottom Layer w20: J102.19 v1(3072.01,3747.99) ; J101.19 v1(3862.01,2377.99) ; v1(3961.39,3715) C101.1@3994,3715 ; v1(3961.39,3745) C101.1@3994,3745 ; C103.1 v1(4200,3405) ; v1(4170.47,3621.53) C102.1 ; v1(4220,3595) 4236.26,3578.74 C104.1
  other v1: 4137.61,2373 4078.11,2373.5 4196.61,2373.5 4019.11,2375 5650.1,3050 5675,3071 5623,3073 3073.5,3414.39 3073,3473.39 3073.5,3532.89 3075,3591.89
  other v2: 3790,2345 3785,2570 3785,2710 3785,2860 3790,3055 3790,3210
GPU_SEL: R108.1 SW101.7 U101.2 | length 908.2
  Top Layer w9: U101.2 4312.8,3362.2 v1(4330,3345) ; v1(4305,3865) SW101.7
  Bottom Layer w9: v1(4305,3865) 4420,3750 4420,3410 4355,3345 v1(4330,3345)
HPDA: J101.18 U101.16 | length 2218.1
  Top Layer w8: v1(3850,2455) 3850,2435 3881.69,2403.31 J101.18 ; v1(3850,3860) 4175,3860 4325,3710 4325,3655 4307.8,3637.8 U101.16
  Bottom Layer w8: v1(3850,2455) v1(3850,3860)
HPDB: J102.18 U101.15 | length 1643
  Top Layer w8: J102.18 3143.31,3728.31 3300,3885 4185,3885 4350,3720 4350,3640 4328.11,3618.11 U101.15
NetC105_2: C105.2 J103.1 | length 281
  Top Layer w6: C105.2 5200,3290 5215.5,3305.5 5235.5,3305.5 5244.73,3314.73 ; 5296.4,3366.4 5302.39,3372.39 5314.5,3372.39 5320,3366.89 v1(5340,3366.89)
  Top Layer w9: 5244.73,3314.73 5296.4,3366.4
  Bottom Layer w6: v1(5340,3366.89) 5343.43,3363.46 J103.1
NetC106_2: C106.2 J103.3 | length 282
  Top Layer w6: C106.2 5200,3340 5215.5,3324.5 5227.63,3324.5 5237.36,3334.23 ; 5288.11,3384.98 5294.52,3391.39 5314.5,3391.39 5320,3396.89 v1(5340,3396.89)
  Top Layer w9: 5237.36,3334.23 5288.11,3384.98
  Bottom Layer w6: v1(5340,3396.89) 5345.94,3402.83 J103.3
NetC107_2: C107.2 J103.4 | length 262.7
  Top Layer w6: C107.2 5205,3395 5220.5,3410.5 5235,3410.5 ; 5315.19,3432.39 5334.5,3432.39 5340,3426.89 v1(5360,3426.89)
  Top Layer w9: 5235,3410.5 5282.37,3410.5 5304.26,3432.39 5315.19,3432.39
  Bottom Layer w6: v1(5360,3426.89) 5364.37,3422.52 J103.4
NetC108_2: C108.2 J103.6 | length 263
  Top Layer w6: C108.2 5205,3445 5220.5,3429.5 5235,3429.5 ; 5315.06,3451.39 5334.5,3451.39 5340,3456.89 v1(5360,3456.89)
  Top Layer w9: 5235,3429.5 5274.5,3429.5 5296.39,3451.39 5315.06,3451.39
  Bottom Layer w6: v1(5360,3456.89) 5365,3461.89 J103.6
NetC109_2: C109.2 J103.7 | length 263.6
  Top Layer w6: C109.2 5205,3500 5220.5,3515.5 5235,3515.5 ; 5300.17,3490.5 5314.5,3490.5 5320,3485 v1(5340,3485)
  Top Layer w9: 5235,3515.5 5257.63,3515.5 5282.63,3490.5 5300.17,3490.5
  Bottom Layer w6: v1(5340,3485) 5343.43,3481.57 J103.7
NetC110_2: C110.2 J103.9 | length 264.7
  Top Layer w6: C110.2 5205,3550 5220.5,3534.5 5235,3534.5 ; 5300.04,3509.5 5314.5,3509.5 5320,3515 v1(5340,3515)
  Top Layer w9: 5235,3534.5 5265.5,3534.5 5290.5,3509.5 5300.04,3509.5
  Bottom Layer w6: v1(5340,3515) 5345.94,3520.94 J103.9
NetC111_2: C111.2 J103.10 | length 282.7
  Top Layer w6: C111.2 5205,3605 5220.5,3620.5 5230,3620.5 ; 5324.82,3550.5 5334.5,3550.5 5340,3545 v1(5360,3545)
  Top Layer w9: 5230,3620.5 5237.63,3620.5 5307.63,3550.5 5324.82,3550.5
  Bottom Layer w6: v1(5360,3545) 5364.37,3540.63 J103.10
NetC112_2: C112.2 J103.12 | length 282.9
  Top Layer w6: C112.2 5205,3655 5220.5,3639.5 5229.91,3639.5 ; 5325,3569.5 5334.5,3569.5 5340,3575 v1(5360,3575)
  Top Layer w9: 5229.91,3639.5 5245.5,3639.5 5315.5,3569.5 5325,3569.5
  Bottom Layer w6: v1(5360,3575) 5365,3580 J103.12
NetC113_2: C113.2 J103.15 R101.2 | length 405.1
  Top Layer w6: C113.2 5238.73,3785 5254.23,3769.5 5267.63,3769.5 ; 5325,3650 5335,3650 5342,3657 5342,3673 v1(5335,3680)
  Top Layer w9: 5267.63,3769.5 5286.5,3769.5 5305,3751 5305,3660 5315,3650 5325,3650
  Bottom Layer w6: v1(5335,3680) 5375.94,3639.06 J103.15
NetC114_2: C114.2 J103.17 R102.2 | length 385.7
  Top Layer w6: C114.2 R102.2@5223.76,3735 ; R102.2 5243.73,3736.27 5257.96,3750.5 5266,3750.5 ; 5325,3631 5342.87,3631 5361,3649.13 5361,3674.43 v1(5366.57,3680)
  Top Layer w9: 5266,3750.5 5278.63,3750.5 5286,3743.13 5286,3652.13 5307.13,3631 5325,3631
  Bottom Layer w6: v1@5366.57,3678.43 J103.17
NetD101_2: D101.2 D102.2 JP101.2 | length 114.8
  Top Layer w20: D102.2@3185,3940 v1(3213.7,3940) ; D102.2@3185,3960 v1(3213.7,3960) ; v1(3696.3,2585) D101.2@3725,2585 ; v1(3696.3,2605) D101.2@3725,2605
NetJ103_18: J103.18 R103.2 U101.18 | length 1597.5
  Top Layer w8: v1(5498,3691) 5524.7,3691 R103.2
  Top Layer w9: U101.18 v1(4229.53,3725) ; v1(4810,3900) v1(4965,3900)
  Bottom Layer w8: v1(4965,3900) 5150,3715 5365,3715 5381.89,3698.11 5490.89,3698.11 v1(5498,3691)
  Bottom Layer w9: v1(4229.53,3725) 4229.53,3869.53 4260,3900 v1(4810,3900)
NetR104_1: R104.1 SW101.1 | length 86.4
  Top Layer w9: SW101.1 R104.1
NetR105_1: R105.1 SW101.2 | length 86.4
  Top Layer w9: SW101.2@4305.03,4382.67 R105.1
NetR106_1: R106.1 SW101.3 | length 86.4
  Top Layer w9: SW101.3 R106.1
NetR110_2: R110.2 R111.1 U102.1 | length 175.4
  Top Layer w9: U102.1 4974.94,2809.35 R110.2 4991.81,2800.27 R111.1
OE: R107.1 SW101.8 U101.25 | length 1005
  Top Layer w9: v1(4096.57,3598.43) U101.25 ; v1(4355,3965) SW101.8
  Bottom Layer w9: v1(4096.57,3598.43) 4096.57,3678.43 4085,3690 3945,3690 3925,3710 3925,3795 4095,3965 v1(4355,3965)
pads on no net: ?. J103.23 J103.24 J103.25 J104.2 J104.3 J104.4 J104.10 J104.11 SW101.4 SW101.5

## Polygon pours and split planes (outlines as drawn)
+3V3 on Top Layer "MidLayer1-No Net" (solid, remove dead copper, pour order 1002): 4900,3105 4420,3105 4420,3250 4900,3250 4900,3105
+3V3_USB on Top Layer "MidLayer1-No Net" (solid, remove dead copper, pour order 1001): 4840,2965 5145,2965 5145,3090 4840,3090 4840,2965
+5V on Top Layer "MidLayer1-No Net" (solid, remove dead copper, pour order 1000): 5068,2926 5072,2930 5553,2930 5578,2905 5705,2905 5705,2850 5575,2850 5544,2819 5494,2769 5162,2769 5070,2769 5068,2771 5068,2926
GND on InternalPlane1 (split plane): 5823.48,4678.35 5846.56,4673.76 5868.84,4666.19 5889.94,4655.78 5909.51,4642.71 5927.2,4627.2 5942.71,4609.51 5955.79,4589.94 5966.19,4568.84 5973.76,4546.56 5978.35,4523.48 5979.82,4501.05 5979.61,4500 5979.61,2620.39 4539,2620.39 4531.2,2618.84 4524.58,2614.42 4424.58,2514.42 4420.16,2507.8 4418.61,2500 4418.61,2208.8 4390.89,2122.39 4336.16,2122.39 4336.16,2199 4334.61,2206.8 4330.19,2213.42 4323.57,2217.84 4315.77,2219.39 3757.16,2219.39 3757.16,2333 3755.61,2340.8 3751.19,2347.42 3744.57,2351.84 3736.77,2353.39 3697.77,2353.39 3689.96,2351.84 3683.35,2347.42 3678.93,2340.8 3677.38,2333 3677.38,2217.45 3671.35,2213.42 3666.93,2206.8 3665.38,2199 3665.38,2122.39 3610.51,2122.39 3583.86,2203.18 3583.86,2957.53 3582.31,2965.33 3577.89,2971.95 3363.65,3186.19 3357.04,3190.61 3349.23,3192.16 2908.8,3192.16 2822.39,3219.87 2822.39,3274.61 2899,3274.61 2906.8,3276.16 2913.42,3280.58 2917.84,3287.2 2919.39,3295 2919.39,3853.61 3033,3853.61 3040.8,3855.16 3047.42,3859.58 3051.84,3866.2 3053.39,3874 3053.39,3913 3051.84,3920.8 3047.42,3927.42 3040.8,3931.84 3033,3933.39 2917.45,3933.39 2913.42,3939.42 2906.8,3943.84 2899,3945.39 2822.39,3945.39 2822.39,4000.25 2903.18,4026.91 3348.3,4026.91 3356.1,4028.46 3362.72,4032.88 3514.42,4184.58 3518.84,4191.2 3520.39,4199 3520.39,4679.61 5800,4679.61 5801.05,4679.82
+3V3 on InternalPlane2 (split plane): 5634.8,4195.78 5634.8,3254.22 5480.78,3100.2 4400,3100.2 4396.1,3099.42 4392.79,3097.21 4390.58,3093.9 4389.8,3090 4389.8,2745 4390.58,2741.1 4392.79,2737.79 4520.37,2610.21 4424.58,2514.42 4420.16,2507.8 4418.61,2500 4418.61,2208.8 4390.89,2122.39 4336.16,2122.39 4336.16,2199 4334.61,2206.8 4330.19,2213.42 4323.57,2217.84 4315.77,2219.39 3975.2,2219.39 3975.2,2405 3974.42,2408.9 3972.21,2412.21 3955.2,2429.22 3955.2,3360.78 4142.21,3547.79 4144.42,3551.1 4145.2,3555 4145.2,3650 4144.42,3653.9 4142.21,3657.21 4102.21,3697.21 4098.9,3699.42 4095,3700.2 3990,3700.2 3986.1,3699.42 3982.79,3697.21 3736.77,3451.19 3610.2,3577.76 3610.2,3810.78 4174.22,4374.8 5455.78,4374.8
GND on InternalPlane2 (split plane): 4124.8,3645.78 4124.8,3559.22 3937.79,3372.21 3935.58,3368.9 3934.8,3365 3934.8,2425 3935.58,2421.1 3937.79,2417.79 3954.8,2400.78 3954.8,2219.39 3757.16,2219.39 3757.16,2333 3755.61,2340.8 3751.19,2347.42 3746.96,2350.24 3746.96,3432.54 3994.22,3679.8 4090.78,3679.8
NetD101_2 on InternalPlane2 (split plane): 5823.48,4678.35 5846.56,4673.76 5868.84,4666.19 5889.94,4655.78 5909.51,4642.71 5927.2,4627.2 5942.71,4609.51 5955.79,4589.94 5966.19,4568.84 5973.76,4546.56 5978.35,4523.48 5979.82,4501.05 5979.61,4500 5979.61,2620.39 4539.03,2620.39 4410.2,2749.22 4410.2,3079.8 5485,3079.8 5488.9,3080.58 5492.21,3082.79 5652.21,3242.79 5654.42,3246.1 5655.2,3250 5655.2,4200 5654.42,4203.9 5652.21,4207.21 5467.21,4392.21 5463.9,4394.42 5460,4395.2 4170,4395.2 4166.1,4394.42 4162.79,4392.21 3592.79,3822.21 3590.58,3818.9 3589.8,3815 3589.8,3573.54 3590.58,3569.63 3592.79,3566.33 3726.57,3432.54 3726.57,2353.39 3697.77,2353.39 3689.96,2351.84 3683.35,2347.42 3678.93,2340.8 3677.38,2333 3677.38,2217.45 3671.35,2213.42 3666.93,2206.8 3665.38,2199 3665.38,2122.39 3610.51,2122.39 3583.86,2203.18 3583.86,2957.53 3582.31,2965.33 3577.89,2971.95 3363.65,3186.19 3357.04,3190.61 3349.23,3192.16 2908.8,3192.16 2822.39,3219.87 2822.39,3274.61 2899,3274.61 2906.8,3276.16 2913.42,3280.58 2917.84,3287.2 2919.39,3295 2919.39,3853.61 3033,3853.61 3040.8,3855.16 3047.42,3859.58 3051.84,3866.2 3053.39,3874 3053.39,3913 3051.84,3920.8 3047.42,3927.42 3040.8,3931.84 3033,3933.39 2917.45,3933.39 2913.42,3939.42 2906.8,3943.84 2899,3945.39 2822.39,3945.39 2822.39,4000.25 2903.18,4026.91 3348.3,4026.91 3356.1,4028.46 3362.72,4032.88 3514.42,4184.58 3518.84,4191.2 3520.39,4199 3520.39,4679.61 5800,4679.61 5801.05,4679.82

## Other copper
Top Layer:
  text "TOP LAYER" at 7201,2281 h80
  text "1" at 7851,2151 h80
Bottom Layer:
  text "BOTTOM LAYER" at 7201,2281 h80
  text "4" at 7851,2151 h80
InternalPlane1 (plane layer: these items are gaps in the copper):
  text "POWER PLANE LAYER" at 7201,2281 h80
  text "2" at 7851,2151 h80
InternalPlane2 (plane layer: these items are gaps in the copper):
  lines w20: 3736.77,2199 3736.77,3436.77 ; 3965,2199 3965,2405 3945,2425 3945,3365 4135,3555 4135,3650 4095,3690 3990,3690 3736.77,3436.77 ; 4545,2600 4400,2745 4400,3090 5485,3090 5645,3250 5645,4200 5460,4385 4170,4385 3600,3815 3600,3573.54 3736.77,3436.77
  text "GND PLANE LAYER" at 7201,2281 h80
  text "3" at 7851,2151 h80

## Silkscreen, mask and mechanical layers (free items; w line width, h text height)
Top Overlay:
  rectangle: 4705,4165 5325,4300
  lines w8: 4600,4000 4600,4140 5400,4140 5400,4000 4600,4000
  text "PI3VDP12412ZHE_DP SW_EVB" at 4600,4380 h60
  text "Date:2012.6.28" at 4900,4320 h60
  text "REV.B" at 4600,4315 h60
  text "S/N:" at 4600,4220 h60
  text "AUX_HPD_SEL" at 4240,3975 h40 r270
  text "GPU_SEL" at 4285,3900 h40 r270
  text "OE" at 4340,3900 h60 r270
  text "+3.3V" at 4305,3115 h60
  text "TOP SILKSCREEN LAYER" at 7201,2281 h80
  text "5" at 7851,2151 h80
Bottom Overlay:
  text "1228DB192" at 5680,2655 h60
  text "BOTTOM SILKSCREEN LAYER" at 7201,2281 h80
  text "6" at 7851,2151 h80
Top Paste:
  text "TOP PASTE LAYER" at 7201,2281 h80
  text "TOP PASTE LAYER" at 7201,2281 h80
  text "TP" at 7831,2151 h80
Bottom Paste:
  text "BOTTOM PASTE LAYER" at 7201,2281 h80
  text "BOTTOM PASTE LAYER" at 7201,2281 h80
  text "BP" at 7831,2151 h80
Top Solder:
  text "TOP SOLDER LAYER" at 7201,2281 h80
  text "7" at 7851,2151 h80
Bottom Solder:
  text "BOTTOM SOLDER LAYER" at 7201,2281 h80
  text "8" at 7851,2151 h80
Drill Guide:
  text "DRILL GUIDE LAYER" at 7201,2281 h80
  text "10" at 7831,2151 h80
Mechanical 1:
  lines w7.99: 5800,4700 cw(c5800,4500) 6000,4500
  lines w8: 5800,4700 3500,4700 3500,4199 3348.3,4047.3 3200,4047.3 2899.9,4047.3 2802,4015 2802,3925 2899,3925 2899,3913 3033,3913 3033,3874 2899,3874 2899,3295 2802,3295 2802,3205 2905.6,3171.77 3200,3171.77 3349.23,3171.77 3563.47,2957.53 3563.47,2500 3563.47,2199.9 3595.77,2102 3685.77,2102 3685.77,2199 3697.77,2199 3697.77,2333 3736.77,2333 3736.77,2199 4315.77,2199 4315.77,2102 4405.77,2102 4439,2205.6 4439,2500 4539,2600 6000,2600 6000,4500
  lines w10: 7171,2241 7171,2631 ; 7571,2111 7571,2241 ; 7571,2371 7571,2501 ; 8101,2371 8101,2501
  lines w12: 6651,2241 9031,2241 ; 6651,2371 9031,2371 ; 6651,2501 9031,2501 ; 6651,2631 9031,2631 ; 6651,2691 7101,2691 ; 6651,2741 7011,2741 ; 6651,2791 7101,2791 ; 8191,2691 8966,2691 ; 8191,2791 8976,2791 ; 8281,2741 8901,2741
  lines w15: 6651,2111 9031,2111 9031,2861 6651,2861 6651,2111
  text "Pericom" at 7331,2691 h180
  text "PCB NAME" at 6691,2541 h60
  text "PI3VDP12412ZHE_DP SW_EVB" at 7201,2541 h80
  text "REV.B" at 8660,2540 h80
  text "DATE" at 6781,2411 h60
  text "6/28/2012" at 7191,2411 h80
  text "Drawn by" at 7601,2411 h60
  text "Haojie Ci" at 8211,2411 h80
  text "TITLE" at 6761,2281 h60
  text "SHEET NUMBER" at 6771,2151 h60
  text "OF       10" at 8071,2151 h80
Drill Drawing:
  lines w10: 7118,3608 7118,4098 ; 7188,2978 7398,2978 ; 7188,3318 7398,3318 ; 7268,3038 7288,2978 ; 7268,3258 7288,3318 ; 7288,3088 7288,2978 ; 7288,3208 7288,3318 ; 7308,3038 7288,2978 ; 7308,3258 7288,3318 ; 7508,3608 7508,4098 ; 8418,3608 8418,4098 ; 9548,3608 9548,4098 ; 7488,2978 7488,3028 8528,3028 8528,2978 7488,2978 ; 7488,3172 7488,3222 8528,3222 8528,3172 7488,3172 ; 7488,3268 8528,3268 8528,3318 7488,3318 7488,3268 ; 7490,3082 8530,3082 8530,3132 7490,3132 7490,3082
  lines w12: 6628,3738 10148,3738 ; 6628,3868 10148,3868
  lines w15: 6628,3608 6628,4098 10148,4098 10148,3608 6628,3608
  text "IMPEDANCE CHART" at 6628,4128 h100
  text "TRACE" at 7178,3988 h60
  text "SINGLE-ENDED" at 7528,3988 h60
  text "DIFFERENTIAL-ENDED" at 8468,3988 h60
  text "LAYER(S)" at 6668,3948 h60
  text "TOLERANCE" at 9588,3948 h60
  text "TYPE" at 7178,3908 h60
  text "IMPEDANCE REQ'D" at 7528,3908 h60
  text "IMPEDANCE REQ'D" at 8468,3908 h60
  text "+/- 10%" at 9728,3788 h80
  text "1" at 6858,3778 h80
  text "--" at 7908,3778 h80
  text "100ohm" at 8853,3773 h80
  text "9/10/9mil" at 7160,3769 h80
  text "9/10/9mil" at 7165,3649 h80
  text "4" at 6858,3648 h80
  text "--" at 7908,3648 h80
  text "100ohm" at 8848,3648 h80
  text "+/- 10%" at 9728,3648 h80
  text "LAYER1 SIGNAL" at 8568,3268 h80
  text "LAYER2 GROUND PLANE" at 8569,3165 h80
  text "THICKNESS is 1.6mm" at 6668,3128 h80
  text "LAYER3 PWR PLANE" at 8569,3076 h80
  text "LAYER4 SIGNAL" at 8568,2978 h80
  text "DRILL DRAWING LAYER" at 7201,2281 h80
  text "9" at 7851,2151 h80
